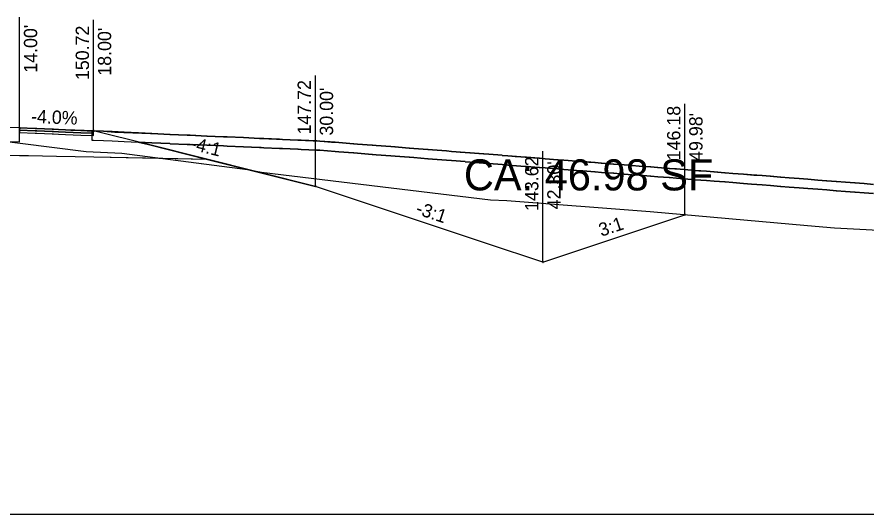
# Model space of a CAD drawing. Extents: x -26 to 4403, y -13 to 9578.
# Drawn here: x 263.87 to 309.83, y 1500 to 1526.88 of the extents above; entities that cross this region are included whole.
import ezdxf

# ---------------------------------------------------------------- set-up
doc = ezdxf.new("R2010")
doc.units = 0
for name, color, linetype in [('_CIVIL_CONSTRUCTION', 7, 'Continuous'), ('CONST_DCH', 7, 'Continuous'), ('CONST_LV3', 7, 'Continuous'), ('DTM_CORRIDOR', 7, 'Continuous'), ('DTM_P_FINISHED_GRADE', 7, 'Continuous'), ('DTM_TEMP_DROP', 7, 'Continuous'), ('DTM_X_GROUND', 7, 'Continuous'), ('SLOPE_STAKES_FILL', 7, 'Continuous'), ('XS_CELL', 7, 'Continuous'), ('XS_M_SHAPES_EARTHWORK', 7, 'Continuous'), ('XS_P_ASPHALT', 7, 'Continuous'), ('XS_P_DR_ASPHALT', 7, 'Continuous'), ('XS_P_DR_ASPHALT_B', 7, 'Continuous'), ('XS_P_DR_GRAVEL', 7, 'Continuous'), ('XS_P_GROUND', 7, 'Continuous'), ('XS_P_SHOULDER', 7, 'Continuous'), ('XS_P_SUBGRADE_GRANULAR', 7, 'Continuous'), ('XS_P_TX_CLEARZONE', 7, 'Continuous'), ('XS_P_TX_FS_BS', 7, 'Continuous'), ('XS_SHEET_EW_TX_AREA', 7, 'Continuous')]:
    doc.layers.add(name, color=color, linetype=linetype)

msp = doc.modelspace()

# ---------------------------------------------------------------- linework, layer by layer
at = {"layer": 'CONST_LV3'}
for points in [[(264, 1520.878), (264, 1520.878), (264.855, 1520.844), (264.916, 1520.842), (264.939, 1520.841), (265.777, 1520.807), (265.788, 1520.807), (265.833, 1520.805), (265.864, 1520.804), (266.708, 1520.77), (266.749, 1520.768), (266.782, 1520.767), (267.626, 1520.733), (267.665, 1520.731), (267.7, 1520.73), (268.544, 1520.696), (269.159, 1520.659), (270.13, 1520.617), (271.083, 1520.577), (271.198, 1520.569), (272.14, 1520.529), (273.063, 1520.489), (273.22, 1520.48), (274.133, 1520.441), (275.027, 1520.402), (275.224, 1520.392), (276.109, 1520.354), (276.976, 1520.316), (277.05, 1520.313), (277.901, 1520.276), (278.053, 1520.269), (278.209, 1520.263), (279.057, 1520.226), (279.887, 1520.19), (280.061, 1520.182), (280.88, 1520.118), (281.065, 1520.104), (281.873, 1520.041), (282.069, 1520.026), (282.866, 1519.963), (283.073, 1519.947), (283.283, 1519.931), (284.076, 1519.869), (284.298, 1519.851), (285.08, 1519.79), (285.845, 1519.73), (286.084, 1519.712), (286.838, 1519.653), (287.088, 1519.633), (287.831, 1519.575), (288.092, 1519.555), (288.358, 1519.534), (289.095, 1519.476), (289.373, 1519.454), (290.099, 1519.398), (290.81, 1519.342), (291.103, 1519.319), (291.803, 1519.264), (292.107, 1519.241), (292.796, 1519.187), (293.111, 1519.162), (293.789, 1519.109), (294.115, 1519.084), (294.782, 1519.031), (295.118, 1519.005), (295.462, 1518.978), (296.122, 1518.927), (296.768, 1518.876), (297.126, 1518.848), (297.761, 1518.798), (298.13, 1518.77), (298.507, 1518.74), (299.134, 1518.691), (299.747, 1518.643), (300.138, 1518.613), (300.74, 1518.565), (301.141, 1518.534), (301.552, 1518.502), (302.145, 1518.456), (302.725, 1518.41), (303.149, 1518.377), (303.718, 1518.332), (304.153, 1518.299), (304.597, 1518.264), (305.157, 1518.22), (305.704, 1518.177), (306.16, 1518.142), (306.697, 1518.1), (307.164, 1518.063), (307.642, 1518.026), (308.168, 1517.985), (308.683, 1517.944), (309.172, 1517.906), (309.676, 1517.867), (310.176, 1517.828)], [(274.174, 1519.175), (280, 1517.718)]]:
    msp.add_lwpolyline(points, dxfattribs=at)
at = {"layer": 'DTM_P_FINISHED_GRADE'}
for points in [[(264, 1520.878), (264, 1520.878), (264.855, 1520.844), (264.916, 1520.842), (264.939, 1520.841), (265.777, 1520.807), (265.788, 1520.807), (265.833, 1520.805), (266.115, 1520.791), (266.481, 1520.779), (267.318, 1520.745), (268, 1520.718)], [(267.906, 1520.722), (267.907, 1520.722), (268, 1520.718), (268.544, 1520.696), (268.551, 1520.696), (269.006, 1520.678), (269.654, 1520.644), (269.666, 1520.644), (270.422, 1520.612), (270.434, 1520.612), (271.15, 1520.582), (272.14, 1520.529), (272.154, 1520.528), (273.063, 1520.489), (273.077, 1520.489), (273.234, 1520.48), (274.133, 1520.441), (274.147, 1520.44), (275.027, 1520.402), (275.041, 1520.402), (275.237, 1520.392), (276.109, 1520.354), (276.123, 1520.353), (276.976, 1520.316), (277.05, 1520.313), (277.063, 1520.312), (277.207, 1520.306), (278.053, 1520.269), (278.066, 1520.269), (278.222, 1520.262), (279.057, 1520.226), (279.07, 1520.225), (279.237, 1520.218), (280.061, 1520.182), (280.074, 1520.182), (280.251, 1520.168), (281.065, 1520.104), (281.077, 1520.103), (281.266, 1520.088), (282.069, 1520.026), (282.081, 1520.025), (282.281, 1520.009), (283.073, 1519.947), (283.085, 1519.946), (283.296, 1519.93), (284.076, 1519.869), (284.088, 1519.868), (284.31, 1519.85), (285.08, 1519.79), (285.092, 1519.789), (285.325, 1519.771), (286.084, 1519.712), (286.096, 1519.711), (286.34, 1519.691), (287.088, 1519.633), (287.099, 1519.632), (287.355, 1519.612), (288.092, 1519.555), (288.103, 1519.554), (288.369, 1519.533), (289.095, 1519.476), (289.107, 1519.475), (289.384, 1519.453), (290.099, 1519.398), (290.11, 1519.397), (290.399, 1519.374), (291.103, 1519.319), (291.114, 1519.318), (291.414, 1519.295), (292.107, 1519.241), (292.118, 1519.24), (292.428, 1519.215), (293.111, 1519.162), (293.121, 1519.161), (293.443, 1519.136), (294.115, 1519.084), (294.125, 1519.083), (294.458, 1519.057), (295.118, 1519.005), (295.129, 1519.004), (295.473, 1518.977), (296.122, 1518.927), (296.132, 1518.926), (296.487, 1518.898), (297.126, 1518.848), (297.136, 1518.847), (297.502, 1518.819), (298.13, 1518.77), (298.139, 1518.769), (298.517, 1518.739), (299.134, 1518.691), (299.143, 1518.69), (299.532, 1518.66), (300.138, 1518.613), (300.147, 1518.612), (300.546, 1518.581), (301.141, 1518.534), (301.15, 1518.533), (301.561, 1518.501), (302.145, 1518.456), (302.154, 1518.455), (302.576, 1518.422), (303.149, 1518.377), (303.158, 1518.376), (303.591, 1518.342), (304.153, 1518.299), (304.161, 1518.298), (304.605, 1518.263), (305.157, 1518.22), (305.165, 1518.219), (305.62, 1518.184), (306.16, 1518.142), (306.169, 1518.141), (306.635, 1518.104), (307.164, 1518.063), (307.172, 1518.062), (307.65, 1518.025), (308.168, 1517.985), (308.176, 1517.984), (308.664, 1517.946), (309.172, 1517.906), (309.18, 1517.905), (309.679, 1517.866), (310.176, 1517.828)]]:
    msp.add_lwpolyline(points, dxfattribs=at)
at = {"layer": 'DTM_X_GROUND'}
msp.add_lwpolyline([(262.308, 1520.28), (267.608, 1519.607), (269.532, 1519.51), (276.336, 1518.635), (277.085, 1518.481), (289.466, 1516.992), (290.351, 1516.958), (298.112, 1516.358), (306.607, 1515.6), (308.072, 1515.483), (315.908, 1515.07), (328.844, 1514.348), (332.234, 1514.262), (338.414, 1514.095), (347.871, 1513.84), (348.208, 1513.842), (349.143, 1513.812), (376.688, 1513.569), (384.125, 1513.444), (384.178, 1513.434), (400, 1513.374)], dxfattribs=at)
at = {"layer": 'XS_CELL'}
msp.add_line((250, 1500), (400, 1500), dxfattribs=at)
at = {"layer": 'XS_M_SHAPES_EARTHWORK'}
for points in [[(262.308, 1520.28), (267.608, 1519.607), (269.532, 1519.51), (271.758, 1519.223), (268.025, 1519.298), (266, 1519.338), (264.495, 1519.369), (264, 1519.378), (253.468, 1519.589)], [(310.176, 1517.328), (309.679, 1517.366), (309.18, 1517.405), (309.172, 1517.406), (308.664, 1517.446), (308.176, 1517.484), (308.168, 1517.485), (307.65, 1517.525), (307.172, 1517.562), (307.164, 1517.563), (306.635, 1517.604), (306.169, 1517.641), (306.16, 1517.642), (305.62, 1517.684), (305.165, 1517.719), (305.157, 1517.72), (304.605, 1517.763), (304.161, 1517.798), (304.153, 1517.799), (303.591, 1517.842), (303.158, 1517.876), (303.149, 1517.877), (302.576, 1517.922), (302.154, 1517.955), (302.145, 1517.956), (301.561, 1518.001), (301.15, 1518.033), (301.141, 1518.034), (300.546, 1518.081), (300.147, 1518.112), (300.138, 1518.113), (299.532, 1518.16), (299.143, 1518.19), (299.134, 1518.191), (298.517, 1518.239), (298.139, 1518.269), (298.13, 1518.27), (297.502, 1518.319), (297.136, 1518.347), (297.126, 1518.348), (296.487, 1518.398), (296.132, 1518.426), (296.122, 1518.427), (295.473, 1518.477), (295.129, 1518.504), (295.118, 1518.505), (294.458, 1518.557), (294.125, 1518.583), (294.115, 1518.584), (293.443, 1518.636), (293.121, 1518.661), (293.111, 1518.662), (292.428, 1518.715), (292.118, 1518.74), (292.107, 1518.741), (291.414, 1518.795), (291.114, 1518.818), (291.103, 1518.819), (290.399, 1518.874), (290.11, 1518.897), (290.099, 1518.898), (289.384, 1518.953), (289.107, 1518.975), (289.095, 1518.976), (288.369, 1519.033), (288.103, 1519.054), (288.092, 1519.055), (287.355, 1519.112), (287.099, 1519.132), (287.088, 1519.133), (286.34, 1519.191), (286.096, 1519.211), (286.084, 1519.212), (285.325, 1519.271), (285.092, 1519.289), (285.08, 1519.29), (284.31, 1519.35), (284.088, 1519.368), (284.076, 1519.369), (283.296, 1519.43), (283.085, 1519.446), (283.073, 1519.447), (282.281, 1519.509), (282.081, 1519.525), (282.069, 1519.526), (281.266, 1519.588), (281.077, 1519.603), (281.065, 1519.604), (280.251, 1519.668), (280.074, 1519.682), (280.061, 1519.682), (279.237, 1519.718), (279.07, 1519.725), (279.057, 1519.726), (278.222, 1519.762), (278.066, 1519.769), (278.053, 1519.769), (277.207, 1519.806), (277.063, 1519.812), (277.05, 1519.813), (276.976, 1519.816), (276.123, 1519.853), (276.109, 1519.854), (275.237, 1519.892), (275.041, 1519.902), (275.027, 1519.902), (274.147, 1519.94), (274.133, 1519.941), (273.234, 1519.98), (273.077, 1519.989), (273.063, 1519.989), (272.154, 1520.028), (272.14, 1520.029), (271.15, 1520.082), (270.434, 1520.112), (270.425, 1520.112), (270.973, 1519.975), (274.174, 1519.175), (271.758, 1519.223), (276.336, 1518.635), (277.085, 1518.481), (289.466, 1516.992), (290.351, 1516.958), (298.112, 1516.358), (306.607, 1515.6), (308.072, 1515.483), (315.908, 1515.07)]]:
    msp.add_lwpolyline(points, dxfattribs=at)
at = {"layer": 'XS_P_ASPHALT'}
msp.add_lwpolyline([(246.532, 1521.089), (236, 1520.878), (236, 1520.693), (236, 1520.128), (246.532, 1520.339), (250, 1520.408), (253.468, 1520.339), (264, 1520.128), (264, 1520.693), (264, 1520.878), (253.468, 1521.089), (250, 1521.158), (246.532, 1521.089)], dxfattribs=at)
at = {"layer": 'XS_P_DR_ASPHALT'}
msp.add_lwpolyline([(264, 1520.878), (264, 1520.753), (264, 1520.753), (264.855, 1520.719), (264.916, 1520.717), (264.939, 1520.716), (265.777, 1520.682), (265.788, 1520.682), (265.833, 1520.68), (266.115, 1520.666), (266.481, 1520.654), (267.318, 1520.62), (268, 1520.593), (268, 1520.593), (268, 1520.718), (268, 1520.718), (267.318, 1520.745), (266.481, 1520.779), (266.115, 1520.791), (265.833, 1520.805), (265.788, 1520.807), (265.777, 1520.807), (264.939, 1520.841), (264.916, 1520.842), (264.855, 1520.844), (264, 1520.878), (264, 1520.878)], dxfattribs=at)
at = {"layer": 'XS_P_DR_ASPHALT_B'}
msp.add_lwpolyline([(264, 1520.753), (264, 1520.628), (264, 1520.628), (264.855, 1520.594), (264.916, 1520.592), (264.939, 1520.591), (265.777, 1520.557), (265.788, 1520.557), (265.833, 1520.555), (266.115, 1520.541), (266.481, 1520.529), (267.318, 1520.495), (268, 1520.468), (268, 1520.468), (268, 1520.593), (268, 1520.593), (267.318, 1520.62), (266.481, 1520.654), (266.115, 1520.666), (265.833, 1520.68), (265.788, 1520.682), (265.777, 1520.682), (264.939, 1520.716), (264.916, 1520.717), (264.855, 1520.719), (264, 1520.753), (264, 1520.753)], dxfattribs=at)
at = {"layer": 'XS_P_DR_GRAVEL'}
for points in [[(267.906, 1520.722), (267.906, 1520.222), (267.907, 1520.222), (268, 1520.218), (268, 1520.218), (268.544, 1520.196), (268.551, 1520.196), (269.006, 1520.178), (269.654, 1520.144), (269.666, 1520.144), (270.422, 1520.112), (270.434, 1520.112), (271.15, 1520.082), (272.14, 1520.029), (272.154, 1520.028), (273.063, 1519.989), (273.077, 1519.989), (273.234, 1519.98), (274.133, 1519.941), (274.147, 1519.94), (275.027, 1519.902), (275.041, 1519.902), (275.237, 1519.892), (276.109, 1519.854), (276.123, 1519.853), (276.976, 1519.816), (277.05, 1519.813), (277.063, 1519.812), (277.207, 1519.806), (278.053, 1519.769), (278.066, 1519.769), (278.222, 1519.762), (279.057, 1519.726), (279.07, 1519.725), (279.237, 1519.718), (280.061, 1519.682), (280.074, 1519.682), (280.251, 1519.668), (281.065, 1519.604), (281.077, 1519.603), (281.266, 1519.588), (282.069, 1519.526), (282.081, 1519.525), (282.281, 1519.509), (283.073, 1519.447), (283.085, 1519.446), (283.296, 1519.43), (284.076, 1519.369), (284.088, 1519.368), (284.31, 1519.35), (285.08, 1519.29), (285.092, 1519.289), (285.325, 1519.271), (286.084, 1519.212), (286.096, 1519.211), (286.34, 1519.191), (287.088, 1519.133), (287.099, 1519.132), (287.355, 1519.112), (288.092, 1519.055), (288.103, 1519.054), (288.369, 1519.033), (289.095, 1518.976), (289.107, 1518.975), (289.384, 1518.953), (290.099, 1518.898), (290.11, 1518.897), (290.399, 1518.874), (291.103, 1518.819), (291.114, 1518.818), (291.414, 1518.795), (292.107, 1518.741), (292.118, 1518.74), (292.428, 1518.715), (293.111, 1518.662), (293.121, 1518.661), (293.443, 1518.636), (294.115, 1518.584), (294.125, 1518.583), (294.458, 1518.557), (295.118, 1518.505), (295.129, 1518.504), (295.473, 1518.477), (296.122, 1518.427), (296.132, 1518.426), (296.487, 1518.398), (297.126, 1518.348), (297.136, 1518.347), (297.502, 1518.319), (298.13, 1518.27), (298.139, 1518.269), (298.517, 1518.239), (299.134, 1518.191), (299.143, 1518.19), (299.532, 1518.16), (300.138, 1518.113), (300.147, 1518.112), (300.546, 1518.081), (301.141, 1518.034), (301.15, 1518.033), (301.561, 1518.001), (302.145, 1517.956), (302.154, 1517.955), (302.576, 1517.922), (303.149, 1517.877), (303.158, 1517.876), (303.591, 1517.842), (304.153, 1517.799), (304.161, 1517.798), (304.605, 1517.763), (305.157, 1517.72), (305.165, 1517.719), (305.62, 1517.684), (306.16, 1517.642), (306.169, 1517.641), (306.635, 1517.604), (307.164, 1517.563), (307.172, 1517.562), (307.65, 1517.525), (308.168, 1517.485), (308.176, 1517.484), (308.664, 1517.446), (309.172, 1517.406), (309.18, 1517.405), (309.679, 1517.366), (310.176, 1517.328)], [(310.176, 1517.828), (309.679, 1517.866), (309.18, 1517.905), (309.172, 1517.906), (308.664, 1517.946), (308.176, 1517.984), (308.168, 1517.985), (307.65, 1518.025), (307.172, 1518.062), (307.164, 1518.063), (306.635, 1518.104), (306.169, 1518.141), (306.16, 1518.142), (305.62, 1518.184), (305.165, 1518.219), (305.157, 1518.22), (304.605, 1518.263), (304.161, 1518.298), (304.153, 1518.299), (303.591, 1518.342), (303.158, 1518.376), (303.149, 1518.377), (302.576, 1518.422), (302.154, 1518.455), (302.145, 1518.456), (301.561, 1518.501), (301.15, 1518.533), (301.141, 1518.534), (300.546, 1518.581), (300.147, 1518.612), (300.138, 1518.613), (299.532, 1518.66), (299.143, 1518.69), (299.134, 1518.691), (298.517, 1518.739), (298.139, 1518.769), (298.13, 1518.77), (297.502, 1518.819), (297.136, 1518.847), (297.126, 1518.848), (296.487, 1518.898), (296.132, 1518.926), (296.122, 1518.927), (295.473, 1518.977), (295.129, 1519.004), (295.118, 1519.005), (294.458, 1519.057), (294.125, 1519.083), (294.115, 1519.084), (293.443, 1519.136), (293.121, 1519.161), (293.111, 1519.162), (292.428, 1519.215), (292.118, 1519.24), (292.107, 1519.241), (291.414, 1519.295), (291.114, 1519.318), (291.103, 1519.319), (290.399, 1519.374), (290.11, 1519.397), (290.099, 1519.398), (289.384, 1519.453), (289.107, 1519.475), (289.095, 1519.476), (288.369, 1519.533), (288.103, 1519.554), (288.092, 1519.555), (287.355, 1519.612), (287.099, 1519.632), (287.088, 1519.633), (286.34, 1519.691), (286.096, 1519.711), (286.084, 1519.712), (285.325, 1519.771), (285.092, 1519.789), (285.08, 1519.79), (284.31, 1519.85), (284.088, 1519.868), (284.076, 1519.869), (283.296, 1519.93), (283.085, 1519.946), (283.073, 1519.947), (282.281, 1520.009), (282.081, 1520.025), (282.069, 1520.026), (281.266, 1520.088), (281.077, 1520.103), (281.065, 1520.104), (280.251, 1520.168), (280.074, 1520.182), (280.061, 1520.182), (279.237, 1520.218), (279.07, 1520.225), (279.057, 1520.226), (278.222, 1520.262), (278.066, 1520.269), (278.053, 1520.269), (277.207, 1520.306), (277.063, 1520.312), (277.05, 1520.313), (276.976, 1520.316), (276.123, 1520.353), (276.109, 1520.354), (275.237, 1520.392), (275.041, 1520.402), (275.027, 1520.402), (274.147, 1520.44), (274.133, 1520.441), (273.234, 1520.48), (273.077, 1520.489), (273.063, 1520.489), (272.154, 1520.528), (272.14, 1520.529), (271.15, 1520.582), (270.434, 1520.612), (270.422, 1520.612), (269.666, 1520.644), (269.654, 1520.644), (269.006, 1520.678), (268.551, 1520.696), (268.544, 1520.696), (268, 1520.718), (268, 1520.718), (267.907, 1520.722), (267.906, 1520.722)]]:
    msp.add_lwpolyline(points, dxfattribs=at)
at = {"layer": 'XS_P_GROUND'}
for points in [[(292.299, 1513.619), (289.249, 1514.636), (280, 1517.718), (270.973, 1519.975), (268, 1520.718)], [(292.299, 1513.619), (299.976, 1516.178)]]:
    msp.add_lwpolyline(points, dxfattribs=at)
at = {"layer": 'XS_P_SHOULDER'}
msp.add_lwpolyline([(268, 1520.718), (264.991, 1520.839), (264, 1520.878)], dxfattribs=at)
at = {"layer": 'XS_P_SUBGRADE_GRANULAR'}
for points in [[(264, 1519.378), (253.468, 1519.589), (250, 1519.658)], [(274.174, 1519.175), (268.025, 1519.298), (266, 1519.338), (264.495, 1519.369), (264, 1519.378)]]:
    msp.add_lwpolyline(points, dxfattribs=at)
at = {"layer": 'XS_P_TX_CLEARZONE'}
for p, q in [((264, 1520.878), (264, 1526.878)), ((264, 1520.878), (264, 1526.878)), ((264, 1520.878), (264, 1526.878)), ((268, 1520.718), (268, 1526.718)), ((268, 1520.718), (268, 1526.718)), ((268, 1520.718), (268, 1526.718)), ((280, 1517.718), (280, 1523.718)), ((280, 1517.718), (280, 1523.718)), ((280, 1517.718), (280, 1523.718)), ((280, 1517.718), (280, 1523.718)), ((280, 1517.718), (280, 1523.718)), ((280, 1517.718), (280, 1523.718)), ((299.976, 1516.178), (299.976, 1522.178)), ((299.976, 1516.178), (299.976, 1522.178)), ((299.976, 1516.178), (299.976, 1522.178)), ((292.299, 1513.619), (292.299, 1519.619)), ((292.299, 1513.619), (292.299, 1519.619)), ((292.299, 1513.619), (292.299, 1519.619))]:
    msp.add_line(p, q, dxfattribs=at)

# ---------------------------------------------------------------- texts
at = {"layer": '_CIVIL_CONSTRUCTION'}
msp.add_text('X', height=0.12, dxfattribs=at).set_placement((263.961, 1520.818))
at = {"layer": 'CONST_DCH'}
msp.add_text('X', height=0.12, dxfattribs=at).set_placement((292.259, 1513.559))
at = {"layer": 'DTM_CORRIDOR'}
msp.add_text('X', height=0.12, dxfattribs=at).set_placement((299.937, 1516.118))
at = {"layer": 'DTM_TEMP_DROP'}
msp.add_text('X', height=0.12, dxfattribs=at).set_placement((267.961, 1520.658))
at = {"layer": 'SLOPE_STAKES_FILL'}
msp.add_text('X', height=0.12, dxfattribs=at).set_placement((279.961, 1517.658))
at = {"layer": 'XS_P_TX_CLEARZONE'}
for s, p in [("14.00'", (264.96, 1523.864)), ("14.00'", (264.96, 1523.864)), ("14.00'", (264.96, 1523.864)), ('150.72', (267.76, 1523.466)), ('150.72', (267.76, 1523.466)), ('150.72', (267.76, 1523.466)), ("18.00'", (268.96, 1523.704)), ("18.00'", (268.96, 1523.704)), ("18.00'", (268.96, 1523.704)), ('147.72', (279.76, 1520.523)), ('147.72', (279.76, 1520.523)), ('147.72', (279.76, 1520.523)), ('147.72', (279.76, 1520.523)), ('147.72', (279.76, 1520.523)), ('147.72', (279.76, 1520.523)), ("30.00'", (280.96, 1520.466)), ("30.00'", (280.96, 1520.466)), ("30.00'", (280.96, 1520.466)), ("30.00'", (280.96, 1520.466)), ("30.00'", (280.96, 1520.466)), ("30.00'", (280.96, 1520.466)), ('146.18', (299.736, 1519.13)), ('146.18', (299.736, 1519.13)), ('146.18', (299.736, 1519.13)), ("49.98'", (300.936, 1519.096)), ("49.98'", (300.936, 1519.096)), ("49.98'", (300.936, 1519.096)), ('143.62', (292.059, 1516.39)), ('143.62', (292.059, 1516.39)), ('143.62', (292.059, 1516.39)), ("42.30'", (293.259, 1516.48)), ("42.30'", (293.259, 1516.48)), ("42.30'", (293.259, 1516.48))]:
    msp.add_text(s, height=0.72, rotation=90, dxfattribs=at).set_placement(p)
at = {"layer": 'XS_P_TX_FS_BS'}
for s, rotation, p in [('-4.0%', 357.7094, (264.616, 1521.154)), ('-4.0%', 357.7094, (264.616, 1521.154)), ('-4.0%', 357.7094, (264.616, 1521.154)), ('-4:1', 345.9638, (273.193, 1519.73)), ('-4:1', 345.9638, (273.193, 1519.73)), ('-4:1', 345.9638, (273.193, 1519.73)), ('-3:1', 341.5668, (285.384, 1516.24)), ('-3:1', 341.5668, (285.384, 1516.24)), ('-3:1', 341.5668, (285.384, 1516.24)), ('3:1', 18.4349, (295.462, 1514.99)), ('3:1', 18.4349, (295.462, 1514.99)), ('3:1', 18.4349, (295.462, 1514.99))]:
    msp.add_text(s, height=0.72, rotation=rotation, dxfattribs=at).set_placement(p)
at = {"layer": 'XS_SHEET_EW_TX_AREA'}
msp.add_text('CA: 46.98 SF', height=1.68, dxfattribs=at).set_placement((288.032, 1517.5))

doc.saveas('drawing.dxf')
